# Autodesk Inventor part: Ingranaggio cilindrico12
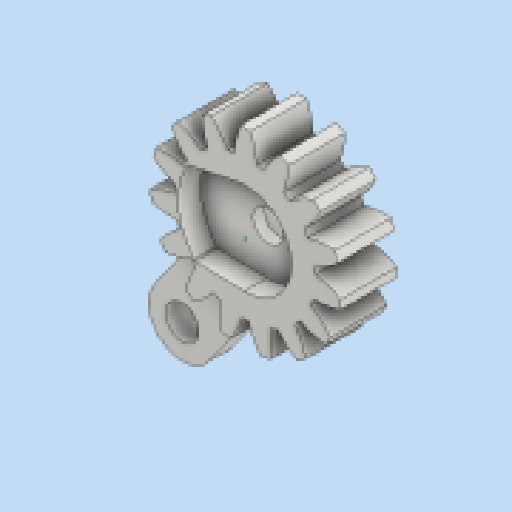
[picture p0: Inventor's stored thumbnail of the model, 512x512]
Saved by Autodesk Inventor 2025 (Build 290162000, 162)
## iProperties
CustomPartVersion: 1
Created: 2026-03
Part Number: Ingranaggio cilindrico12
Material: Steel
Document SubType Name: Modeling
Designer: R5800u
Categories: <?xml version="1.0" encoding="UTF-16"?> <MemberInstance><Categories><FamilyTemplate><FamilyTemplateParameter ValueType="xs:double" Id="1" ObjectReferenceKey="da
Density: 1 g/cm^3
Appearance: Steel
Author: R5800u
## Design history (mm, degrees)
sketch "Sketch1"
  geometry: C1 r 8.5 at (0, 0)
  constraints: 1 centre point
  dimensions: "d0" = 17 diameter of C1 (= da_da)
extrude "Extrusion1" new body sketch "Sketch1" distance "d1" = 5 (= da_b); taper "d2" = 0 deg
workplane "Work Plane2"
feature "Diametro primitivo" dims "d4" = 10, "d5" = 0
workplane "Work Plane8"
workplane "Work Plane9"
feature "Ingranaggio cilindrico" dims "da_b" = 5, "da_d" = 15, "da_aw" = 15, "da_da" = 17, "da_df" = 12.5, "da_dw" = 15, angle "da_beta" = 0 deg, "da_lefttooth" = 0, "da_righttooth" = 0
sketch "Schizzo3"
  geometry: A1 r 6.25 centre (0, 0) between (5.835, -2.24) and (6.037, -1.618) reference; 2 further points
  constraints: 1 coincident
hole "Foro1" sketch "Schizzo3" at (0, 0) diameter "d49" = 2.7; stored, may be unused: countersink angle "d53" = 90 deg, drill point angle "d55" = 118 deg; dims "d50" = 6, "d51" = 4.5, "d52" = 2, "d54" = 8
sketch "Schizzo4"
  geometry: L1 (25.195, -9.923)-(31.073, -6.121) reference; L2 (31.073, -6.121)-(28.357, -1.922) reference; L3 (28.357, -1.922)-(22.48, -5.724) reference; L4 (21.492, -6.959)-(11.416, -13.476) reference; L5 (13.589, -16.835)-(23.664, -10.317) reference; L6 (0, 0)-(11.243, -15.97); L7 (-2.95, -1.02)-(8.79, -17.697); L8 (1.956, 2.433)-(13.696, -14.243); C1 r 1.6 at (11.243, -15.97) reference; C2 r 1.6 at (23.838, -7.823) reference; C3 r 1.35 at (0, 0) reference; C4 r 2.25 at (0, 0) reference; C5 r 3 at (8.635, -12.265); C6 r 1.5 at (8.635, -12.265); A1 r 2.5 centre (23.838, -7.823) between (23.664, -10.317) and (25.195, -9.923) reference; A2 r 2.5 centre (23.838, -7.823) between (22.48, -5.724) and (21.492, -6.959) reference; A3 r 2.5 centre (11.243, -15.97) between (11.416, -13.476) and (13.589, -16.835) reference; A4 r 6.25 centre (0, 0) between (4.419, -4.419) and (4.857, -3.933) reference; 11 further points
  constraints: 6 end point, 2 centre point, 2 coincident, 2 parallel, 1 point on line, 1 tangent, 3 other
  dimensions: "d56" = 3 distance between parallel lines of L6 L7; "d57" = 3 distance between parallel lines of L6 L8; "d61" = 15 distance of point (0, 0) C5.centre; "d62" = 3 diameter of C6
  node "Riferimento1"
node "Piano di lavoro11"
extrude "Estrusione2" join sketch "Schizzo4" stored distance "d58" = 10; taper "d59" = 0 deg
fillet "Raccordo1" dims "d63" = 2.5
sketch "Schizzo6"
  geometry: 1 further point
sketch "Schizzo7"
  geometry: L1 (-0.808, 3.918)-(-5.185, 3.02) reference; L2 (-4.564, -3.894)-(-0.098, -3.999) reference; L3 (-0.828, 4.015)-(-5.249, 3.109); L4 (-4.611, -3.993)-(-0.1, -4.099); L5 (-5.185, 3.02)-(-5.115, 3.136); L6 (-4.564, -3.894)-(-4.475, -3.996); A1 r 6 centre (0, 0) between (-5.185, 3.02) and (-4.564, -3.894) reference; A2 r 4 centre (0, 0) between (-3.914, -0.825) and (-3.998, 0.115) reference; A3 r 4.1 centre (0, 0) between (-4.012, -0.846) and (-4.098, 0.118); A4 r 6.1 centre (0, 0) between (-5.249, 3.109) and (-4.611, -3.993); 5 further points
  constraints: 8 end point, 4 point on circle, 2 centre point, 2 point on line, 2 other
  dimensions: "d64" = 0.1 radial gap between concentric circles of A2 A3; "d65" = 0.1 distance between parallel lines of L1 L3
extrude "Estrusione3" cut sketch "Schizzo7" distance "d66" = 2; taper "d67" = 0 deg
body "Solid1"
sketch "Sketch2"
  geometry: C1 r 8.5 at (0, 0) reference; C2 r 7.5 at (0, 0)
  constraints: 1 centre point, 1 coincident
  dimensions: "d3" = 15 diameter of C2 (= da_d)
body "Srf1"
node "Riferimento2"
node "Riferimento3"
node "Riferimento4"
node "Riferimento5"
other parameters: "d16" = 15 (= da_aw), "d17" = 0, "d34" = 12 deg (computed from da_z), "d39" = 0, "d41" = 0, "d43" = 15 (= da_aw), "d46" = 15 (= da_aw), "d47" = 0, "d48" = 0
